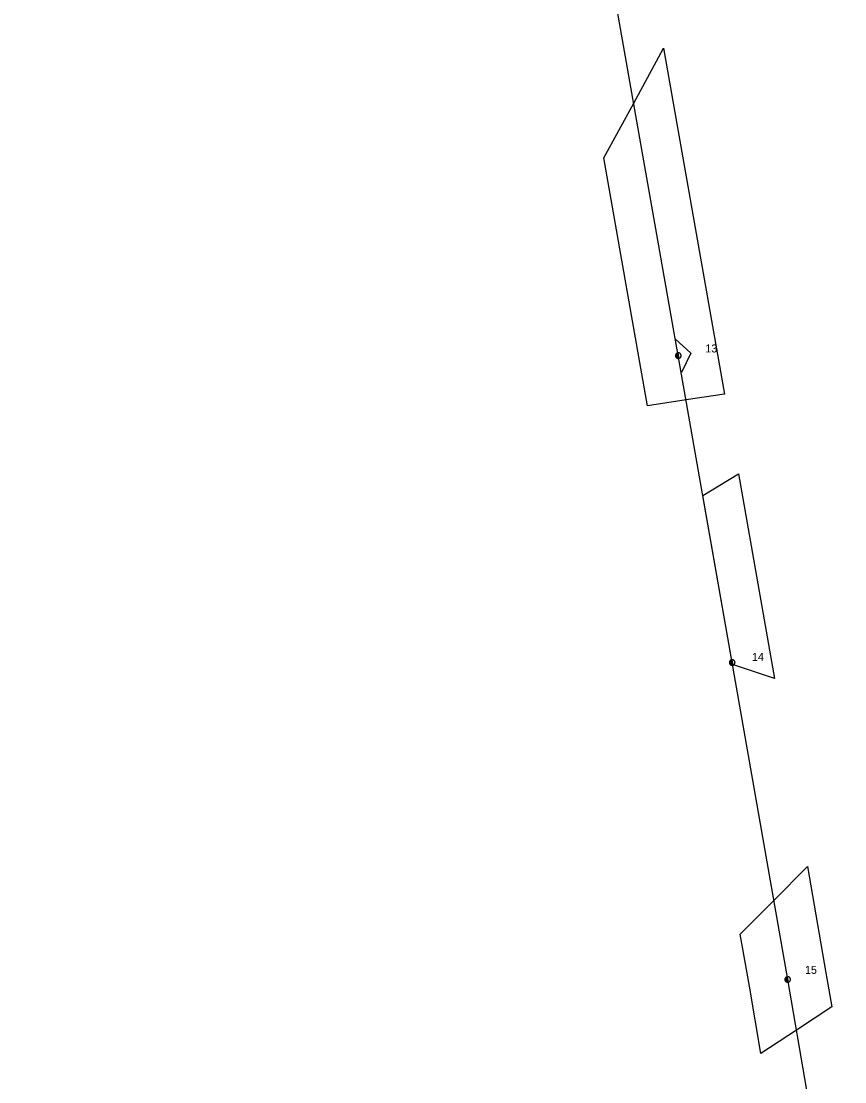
# Model space of a CAD drawing. Extents: x -788491 to -785797, y -1154753 to -1152002.
# Drawn here: x -786883.8 to -786703.8, y -1154520.6 to -1154288.7 of the extents above; entities that cross this region are included whole.
import ezdxf

# ---------------------------------------------------------------- set-up
doc = ezdxf.new("R2010")
doc.units = 0
for name, color, linetype in [('Vrstva 13', 7, 'Continuous'), ('Vrstva 14', 7, 'Continuous'), ('Vrstva 15', 7, 'Continuous'), ('Vrstva 18', 7, 'Continuous'), ('Vrstva 2', 7, 'Continuous'), ('Vrstva 35', 7, 'Continuous'), ('Vrstva 52', 7, 'Continuous')]:
    doc.layers.add(name, color=color, linetype=linetype)

# ---------------------------------------------------------------- blocks, each defined once
blk = doc.blocks.new('VN860')
at = {"layer": 'Vrstva 15'}
for points in [[(-3.74, 0), (0.01, 2.82)], [(0.01, 2.82), (3.76, 0)]]:
    blk.add_lwpolyline(points, dxfattribs=at)
blk = doc.blocks.new('VN440')
at = {"layer": 'Vrstva 2'}
for points in [[(1.22, 0), (1.21, 0.13), (1.19, 0.25), (1.16, 0.38), (1.11, 0.5), (1.05, 0.61), (0.98, 0.72), (0.9, 0.82), (0.81, 0.91), (0.71, 0.99), (0.6, 1.06), (0.49, 1.12), (0.37, 1.16), (0.25, 1.2), (0.12, 1.22), (-0.01, 1.22), (-0.14, 1.22), (-0.26, 1.2), (-0.39, 1.16), (-0.51, 1.12), (-0.62, 1.06), (-0.73, 0.99), (-0.83, 0.91), (-0.92, 0.82), (-1, 0.72), (-1.07, 0.61), (-1.13, 0.5), (-1.18, 0.38), (-1.21, 0.25), (-1.23, 0.13), (-1.24, 0), (-1.23, -0.13), (-1.21, -0.26), (-1.18, -0.38), (-1.13, -0.5), (-1.07, -0.62), (-1, -0.73), (-0.92, -0.83), (-0.83, -0.92), (-0.73, -1), (-0.62, -1.07), (-0.51, -1.13), (-0.39, -1.17), (-0.26, -1.2), (-0.14, -1.23), (-0.01, -1.23), (0.12, -1.23), (0.25, -1.2), (0.37, -1.17), (0.49, -1.13), (0.6, -1.07), (0.71, -1), (0.81, -0.92), (0.9, -0.83), (0.98, -0.73), (1.05, -0.62), (1.11, -0.5), (1.16, -0.38), (1.19, -0.26), (1.21, -0.13), (1.22, 0)], [(-1.24, 0), (1.22, 0)], [(-1.18, -0.34), (1.1, -0.34)], [(-1.01, -0.63), (0.97, -0.63)], [(-0.74, -0.92), (0.68, -0.92)]]:
    blk.add_lwpolyline(points, dxfattribs=at)

msp = doc.modelspace()

# ---------------------------------------------------------------- linework, layer by layer
at = {"layer": 'Vrstva 35'}
for points in [[(-786731.82, -1154360.35), (-786730.09, -1154370.23), (-786738.5, -1154371.5), (-786746.9, -1154372.78), (-786748.57, -1154363.3), (-786756.45, -1154318.53), (-786749.92, -1154306.58), (-786743.4, -1154294.61)], [(-786720.04, -1154427.47), (-786719.18, -1154432.39), (-786728.34, -1154429.36), (-786728.42, -1154428.94), (-786734.84, -1154392.37), (-786727.02, -1154387.68)], [(-786707.91, -1154496.77), (-786706.63, -1154504.2), (-786714.38, -1154509.31), (-786722.12, -1154514.42), (-786724.66, -1154499.68), (-786726.64, -1154488.33), (-786719.31, -1154480.95), (-786711.97, -1154473.55)]]:
    msp.add_lwpolyline(points, close=True, dxfattribs=at)
at = {"layer": 'Vrstva 52'}
msp.add_lwpolyline([(-786703.8, -1154570.83), (-786716.28, -1154498.23), (-786728.41, -1154428.94), (-786740.19, -1154361.82), (-786754.76, -1154279.07), (-786770.29, -1154189.42), (-786783.99, -1154109.49), (-786799.92, -1154016.94), (-786830.62, -1153942.5), (-786855.4, -1153882.26), (-786883.82, -1153812.44)], dxfattribs=at)

# ---------------------------------------------------------------- block references
at = {"layer": 'Vrstva 13'}
for p, xscale, yscale, rotation in [((-786740.19, -1154361.82), 0.5, 0.5000000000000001, -79.60090835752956), ((-786728.41, -1154428.93), 0.5000000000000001, 0.5, -79.30072218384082), ((-786716.28, -1154498.23), 0.5, 0.5, -79.63580281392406)]:
    msp.add_blockref('VN440', p, dxfattribs=dict(at, xscale=xscale, yscale=yscale, rotation=rotation))
at = {"layer": 'Vrstva 18', "rotation": -79.1277028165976}
msp.add_blockref('VN860', (-786740.19, -1154361.82), dxfattribs=at)

# ---------------------------------------------------------------- texts
at = {"layer": 'Vrstva 14'}
for s, p in [('13', (-786734.29, -1154361.12)), ('14', (-786724.09, -1154428.57)), ('15', (-786712.49, -1154497))]:
    msp.add_text(s, height=1.75, dxfattribs=at).set_placement(p)

doc.saveas('drawing.dxf')
